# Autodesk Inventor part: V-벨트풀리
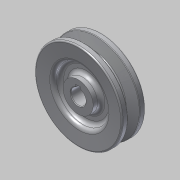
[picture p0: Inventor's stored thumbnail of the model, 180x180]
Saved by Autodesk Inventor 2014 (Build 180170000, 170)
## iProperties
Created: 2016-08
Part Number: V-벨트풀리
Material: 알루미늄 6061
Document SubType Name: Modeling
Designer: mduedu
Density: 2.71 g/cm^3
Appearance: 알루미늄 - 평지
Author: mduedu
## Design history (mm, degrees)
sketch "스케치1"
  geometry: L1 (0, 9.5)-(0, -9.5); L2 (0, 9.5)-(35, 9.5); L3 (35, 9.5)-(35, 4.825); L4 (35, 4.825)-(26, 2.074); L5 (26, 2.074)-(26, 0); L6 (0, 0)-(26, 0); L7 (0, -9.5)-(35, -9.5); L8 (35, -9.5)-(35, -4.825); L9 (35, -4.825)-(26, -2.074); L10 (26, -2.074)-(26, 0); L11 (32.3, 9.5)-(32.3, -9.5); 3 further points
  constraints: 22 end point, 6 point on line, 4 perpendicular, 3 symmetric about line, 1 coincident, 1 horizontal alignment, 1 midpoint, 1 parallel, 1 vertical
  dimensions: "d0" = 19 distance of L1.start L1.end; "d2" = 70 diameter of L8 L1; "d4" = 6.3 distance between parallel lines of L10 L11; "d5" = 2.7 distance between parallel lines of L11 L8; "d6" = 8 distance of point (32.3, -4) point (32.3, 4); "d7" = 34 deg angle of L9 L4
revolve "회전1" sketch "스케치1" stored, may be unused: angle "d8" = 90 deg
sketch "스케치2"
  geometry: L1 (-2, 0)-(2, 0); L2 (2, 0)-(2, 7.8); L3 (2, 7.8)-(-2, 7.8); L4 (-2, 7.8)-(-2, 0); C1 r 6 at (0, 0); 2 further points
  constraints: 8 end point, 2 coincident, 2 parallel, 1 centre point, 1 horizontal, 1 midpoint, 1 perpendicular
  dimensions: "d9" = 12 diameter of C1; "d11" = 4 distance of L2.end L3.end; "d12" = 7.8 distance of L1.end L2.end
extrude "돌출1" cut sketch "스케치2" stored distance "d13" = 10; taper "d14" = 0 deg
sketch "스케치3"
  geometry: L1 (35, 4.825)-(26, 2.074) reference; L2 (26, 2.074)-(26, -2.074) reference; L3 (0, 0)-(26, 0); L4 (35, 9.5)-(35, 4.825) reference; L5 (-35, 9.5)-(35, 9.5) reference; L6 (35, 9.5)-(21, 8.275); L7 (21, 8.275)-(21, 3); L8 (21, 3)-(12, 3); L9 (12, 3)-(12, 9.5); L10 (0, 9.5)-(0, -9.5); L11 (5.657, -9.5)-(-6, -9.5) reference; L12 (12, 9.5)-(35, 9.5)
  constraints: 14 end point, 3 midpoint, 2 perpendicular, 2 point on line, 1 collinear, 1 horizontal, 1 parallel
  dimensions: "d15" = 3 distance between parallel lines of L3 L8; "d17" = 42 diameter of L7 L10; "d18" = 24 diameter of L9 L10; "d31" = 5 deg angle of L6 L5
revolve "회전2" sketch "스케치3" stored, may be unused: angle "d19" = 90 deg
fillet "모깎기1" dims "d20" = 0.5, "d21" = 1, "d22" = 1
fillet "모깎기2" dims "d23" = 3
fillet "모깎기3" dims "d24" = 3
fillet "모깎기4" dims "d25" = 3
chamfer "모따기1" distance "d26" = 0.5; stored, may be unused: second distance "d27" = 2, angle "d28" = 45 deg
node "솔리드1"
mirror "대칭1"
